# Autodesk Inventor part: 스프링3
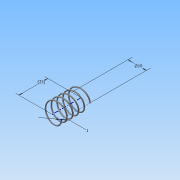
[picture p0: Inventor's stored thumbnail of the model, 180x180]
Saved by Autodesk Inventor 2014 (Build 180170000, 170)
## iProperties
Created: 2015-06
Part Number: 스프링3
Material: Generic
Document SubType Name: Modeling
Designer: Administrator
Density: 1 g/cm^3
Appearance: Default
Author: Administrator
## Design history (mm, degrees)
sketch "스케치1"
  geometry: L1 (0, 0)-(8, 0); L2 (8, 0)-(8, 21.5); L3 (8, 21.5)-(0, 21.5); L4 (0, 21.5)-(0, 0); C1 r 0.5 at (8, 0)
  constraints: 8 end point, 2 parallel, 1 centre point, 1 coincident, 1 horizontal, 1 perpendicular
  dimensions: "d0" = 21.5 distance of L3.end L1.start (derived); "d1" = 16 diameter of L2 L4; "d2" = 1 diameter of C1
feature "코일1" sketch "스케치1" pitch "d3" = 10; turns "d5" = 5; dims "d4" = 21.5 (= d0), "d6" = 0, angle "d7" = 90 deg, angle "d8" = 90 deg, "d9" = 0, "d10" = 0
sketch "스케치2"
  geometry: L1 (-8.5, 0)-(-7.5, 0) reference; 1 further point
  constraints: 1 horizontal alignment
extrude "돌출1" cut sketch "스케치2" stored distance "d11" = 10; taper "d12" = 0 deg
node "작업 평면1"
sketch "스케치3"
  geometry: L1 (-7.5, 0)-(-8.5, 0) reference; 1 further point
  constraints: 1 horizontal alignment
extrude "돌출2" cut sketch "스케치3" stored distance "d14" = 10; taper "d15" = 0 deg
node "솔리드1"
node "절단 모서리 투영1"
node "절단 모서리 투영2"
other parameters: "d13" = 21.5 (= d0)
